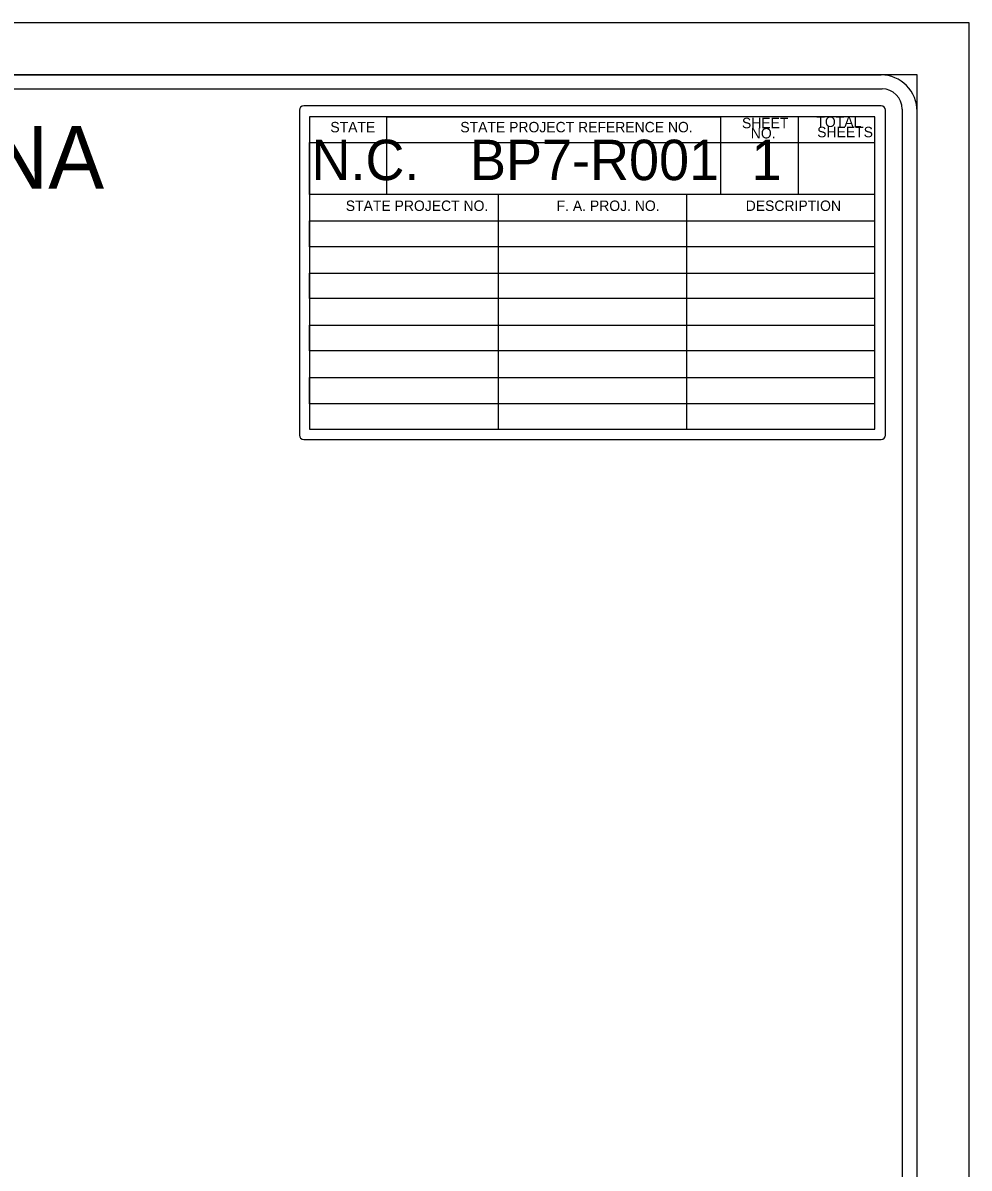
# Model space of a CAD drawing. Extents: x 2538775 to 2540754, y 826823 to 828055.
# Drawn here: x 2540020 to 2540475, y 827397 to 827947 of the extents above; entities that cross this region are included whole.
import ezdxf

# ---------------------------------------------------------------- set-up
doc = ezdxf.new("R2010")
doc.units = 0
for name, color, linetype in [('Old_Level_40', 7, 'Continuous'), ('Old_Level_42', 7, 'Continuous'), ('Old_Level_62', 7, 'Continuous'), ('Old_Level_63', 7, 'Continuous')]:
    doc.layers.add(name, color=color, linetype=linetype)

msp = doc.modelspace()

# ---------------------------------------------------------------- linework, layer by layer
at = {"layer": 'Old_Level_40'}
for p, q in [((2540153.05, 827904.87), (2540153.05, 827748.84)), ((2540432.64, 827907.03), (2540155.18, 827907.03)), ((2540434.77, 827748.84), (2540434.77, 827904.87)), ((2540442.74, 827905.36), (2540442.75, 827407.6)), ((2540449.9, 827407.64), (2540449.9, 827904.38)), ((2540153.05, 827756.5), (2540153.05, 827756.5)), ((2540155.18, 827746.69), (2540432.64, 827746.69)), ((2540442.75, 827407.6), (2540442.74, 827091.26)), ((2540449.9, 826889.31), (2540449.9, 827407.64))]:
    msp.add_line(p, q, dxfattribs=at)
for points in [[(2538967.11, 827921.85), (2540432.69, 827921.85)], [(2539031.49, 827915.17), (2540433.08, 827915.17)], [(2540157.89, 827751.59), (2540429.55, 827751.59), (2540429.55, 827763.76), (2540157.89, 827763.76), (2540157.89, 827776.52), (2540429.55, 827776.52), (2540429.55, 827789.27), (2540157.89, 827789.27), (2540157.89, 827801.64), (2540429.55, 827801.64), (2540429.55, 827814.39), (2540157.89, 827814.39), (2540157.89, 827826.56), (2540429.55, 827826.56), (2540429.55, 827839.32), (2540157.89, 827839.32), (2540157.89, 827851.68), (2540429.55, 827851.68), (2540429.55, 827864.44), (2540157.89, 827864.44), (2540157.89, 827889.36), (2540429.55, 827889.36), (2540429.55, 827901.73), (2540157.89, 827901.73), (2540157.89, 827751.59), (2540248.76, 827751.59), (2540248.76, 827864.44), (2540195.01, 827864.44), (2540195.01, 827901.73), (2540355.49, 827901.73), (2540355.49, 827864.44), (2540339.06, 827864.44), (2540339.06, 827751.59), (2540429.55, 827751.59), (2540429.55, 827901.73), (2540392.81, 827901.73), (2540392.81, 827864.44)]]:
    msp.add_lwpolyline(points, dxfattribs=at)
for centre, major_axis, start_param, end_param in [((2540432.69, 827904.38), (0, 17.47), 4.712393, 6.283192), ((2540433.08, 827905.36), (0, 9.81), 4.712406, 6.2832), ((2540155.18, 827904.87), (0, 2.16), 0, 1.570796), ((2540432.64, 827904.87), (0, 2.16), 4.712389, 6.283185), ((2540432.64, 827904.87), (0, 2.16), 4.712389, 6.283185), ((2540155.18, 827748.84), (0, -2.16), 4.712389, 6.283185), ((2540432.64, 827748.84), (0, 2.16), 3.141593, 4.712389)]:
    msp.add_ellipse(centre, major_axis=major_axis, ratio=0.985213, start_param=start_param, end_param=end_param, dxfattribs=at)
at = {"layer": 'Old_Level_62'}
msp.add_lwpolyline([(2538799.9, 826871.85), (2540449.9, 826871.85), (2540449.9, 827921.85), (2538799.9, 827921.85)], close=True, dxfattribs=at)
at = {"layer": 'Old_Level_63'}
msp.add_lwpolyline([(2538774.9, 826846.85), (2540474.9, 826846.85), (2540474.9, 827946.85), (2538774.9, 827946.85)], close=True, dxfattribs=at)

# ---------------------------------------------------------------- texts
at = {"layer": 'Old_Level_40'}
for s, height, p in [('STATE OF NORTH CAROLINA', 30.0765, (2539491.62, 827867.23)), ('STATE', 5.01, (2540167.94, 827894.27)), ('STATE PROJECT REFERENCE NO.', 5.0104, (2540230.4, 827894.27)), ('N.C.', 19.4, (2540158.86, 827871.31)), ('BP7-R001', 19.4, (2540235.07, 827871.31)), ('1', 19.4, (2540370.36, 827871.31)), ('STATE PROJECT NO.', 5.0104, (2540175.36, 827856.49)), ('F. A. PROJ. NO.', 5.0104, (2540276.68, 827856.49)), ('DESCRIPTION', 5.0104, (2540367.55, 827856.49))]:
    msp.add_text(s, height=height, rotation=360, dxfattribs=at).set_placement(p)
at = {"layer": 'Old_Level_42'}
for s, p in [('SHEET', (2540365.74, 827896.23)), ('TOTAL', (2540401.51, 827896.82)), ('NO.', (2540370, 827891.33)), ('SHEETS', (2540401.9, 827891.91))]:
    msp.add_text(s, height=5.01, rotation=360, dxfattribs=at).set_placement(p)

doc.saveas('drawing.dxf')
